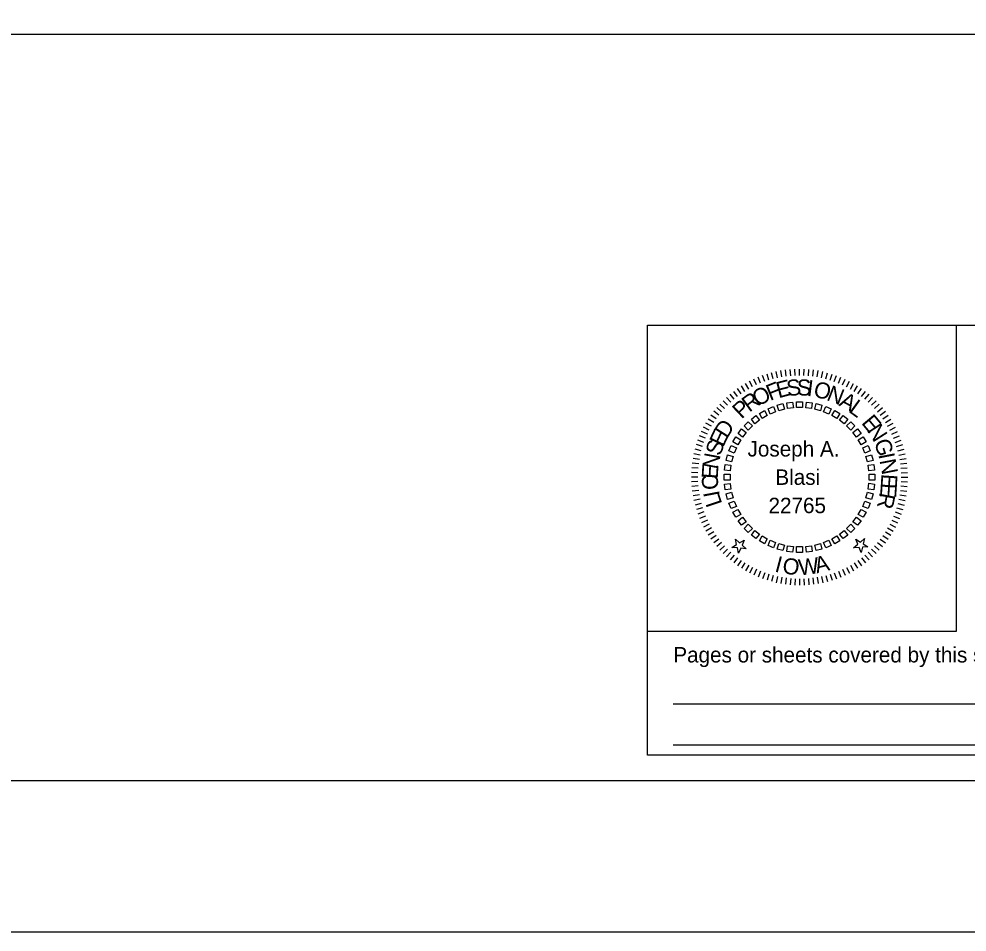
# Model space of a CAD drawing. Extents: x 10040 to 81668, y 7194 to 11018.
# Drawn here: x 11700 to 12436, y 7807 to 8516 of the extents above; entities that cross this region are included whole.
import ezdxf

# ---------------------------------------------------------------- set-up
doc = ezdxf.new("R2010")
doc.units = 0
for name, color, linetype in [('dsnCellElements', 7, 'Continuous'), ('dsnCellsSignature', 7, 'Continuous'), ('dsnTextCpn', 7, 'Continuous'), ('Level 3', 7, 'Continuous'), ('Level 4', 7, 'Continuous')]:
    doc.layers.add(name, color=color, linetype=linetype)

msp = doc.modelspace()

# ---------------------------------------------------------------- linework, layer by layer
at = {"layer": 'dsnCellElements'}
msp.add_lwpolyline([(10039.57, 10000.02), (13360.47, 10000.02), (13360.47, 7806.6), (10039.57, 7806.6)], close=True, dxfattribs=at)
at = {"layer": 'dsnCellsSignature'}
for p, q in [((12428.13, 8040.25), (12428.13, 8278.14)), ((12188.13, 8040.25), (12428.13, 8040.25)), ((12208.2, 7984.02), (12918.13, 7984.02)), ((12208.2, 7952.02), (12918.13, 7952.02))]:
    msp.add_line(p, q, dxfattribs=at)
msp.add_lwpolyline([(12188.13, 8278.14), (12938.13, 8278.14), (12938.13, 7944.02), (12188.13, 7944.02)], close=True, dxfattribs=at)
at = {"layer": 'dsnTextCpn'}
for p, q in [((12282.49, 8235.37), (12280.99, 8240.14)), ((12285.8, 8236.33), (12284.51, 8241.16)), ((12289.15, 8237.15), (12288.07, 8242.03)), ((12292.53, 8237.82), (12291.66, 8242.75)), ((12295.94, 8238.35), (12295.28, 8243.31)), ((12299.37, 8238.72), (12298.93, 8243.71)), ((12302.8, 8238.95), (12302.58, 8243.95)), ((12306.25, 8239.03), (12306.25, 8244.03)), ((12306.25, 8239.03), (12306.25, 8244.03)), ((12309.7, 8238.95), (12309.91, 8243.95)), ((12313.13, 8238.72), (12313.57, 8243.71)), ((12316.56, 8238.35), (12317.21, 8243.31)), ((12319.97, 8237.82), (12320.84, 8242.75)), ((12323.35, 8237.15), (12324.43, 8242.03)), ((12326.7, 8236.33), (12327.99, 8241.16)), ((12330.01, 8235.37), (12331.51, 8240.14)), ((12266.75, 8228.44), (12264.25, 8232.77)), ((12269.77, 8230.1), (12267.46, 8234.53)), ((12272.86, 8231.62), (12270.75, 8236.16)), ((12276.02, 8233.01), (12274.1, 8237.63)), ((12279.23, 8234.26), (12277.52, 8238.96)), ((12333.27, 8234.26), (12334.98, 8238.96)), ((12336.48, 8233.01), (12338.4, 8237.63)), ((12339.64, 8231.62), (12341.75, 8236.15)), ((12342.73, 8230.1), (12345.04, 8234.53)), ((12345.75, 8228.44), (12348.25, 8232.77)), ((12258.15, 8222.7), (12255.11, 8226.67)), ((12260.94, 8224.74), (12258.07, 8228.83)), ((12263.8, 8226.65), (12261.12, 8230.87)), ((12348.7, 8226.65), (12351.38, 8230.87)), ((12351.56, 8224.74), (12354.43, 8228.83)), ((12354.34, 8222.7), (12357.39, 8226.67)), ((12250.39, 8215.89), (12246.85, 8219.42)), ((12252.88, 8218.27), (12249.5, 8221.96)), ((12255.47, 8220.54), (12252.25, 8224.37)), ((12357.03, 8220.54), (12360.25, 8224.37)), ((12359.62, 8218.27), (12363, 8221.95)), ((12362.11, 8215.89), (12365.65, 8219.42)), ((12243.57, 8208.12), (12239.6, 8211.16)), ((12245.73, 8210.8), (12241.9, 8214.02)), ((12248, 8213.4), (12244.32, 8216.77)), ((12364.5, 8213.4), (12368.18, 8216.77)), ((12366.77, 8210.8), (12370.6, 8214.02)), ((12368.93, 8208.12), (12372.89, 8211.16)), ((12239.62, 8202.47), (12235.4, 8205.16)), ((12241.53, 8205.34), (12237.44, 8208.2)), ((12370.97, 8205.34), (12375.06, 8208.2)), ((12372.88, 8202.47), (12377.1, 8205.16)), ((12234.65, 8193.41), (12230.12, 8195.52)), ((12236.17, 8196.5), (12231.74, 8198.81)), ((12237.83, 8199.52), (12233.5, 8202.02)), ((12374.67, 8199.52), (12379, 8202.02)), ((12376.33, 8196.5), (12380.76, 8198.81)), ((12377.85, 8193.41), (12382.38, 8195.52)), ((12232.01, 8187.04), (12227.31, 8188.75)), ((12233.26, 8190.25), (12228.64, 8192.17)), ((12379.24, 8190.25), (12383.86, 8192.17)), ((12380.49, 8187.04), (12385.19, 8188.75)), ((12229.94, 8180.47), (12225.11, 8181.76)), ((12230.9, 8183.78), (12226.13, 8185.28)), ((12381.6, 8183.78), (12386.37, 8185.28)), ((12382.56, 8180.47), (12387.39, 8181.76)), ((12228.45, 8173.74), (12223.52, 8174.61)), ((12229.12, 8177.12), (12224.24, 8178.2)), ((12383.38, 8177.12), (12388.26, 8178.2)), ((12384.05, 8173.74), (12388.98, 8174.61)), ((12227.55, 8166.91), (12222.57, 8167.34)), ((12227.92, 8170.33), (12222.96, 8170.99)), ((12384.58, 8170.33), (12389.53, 8170.99)), ((12384.95, 8166.91), (12389.93, 8167.34)), ((12227.24, 8160.02), (12222.24, 8160.02)), ((12227.32, 8163.47), (12222.33, 8163.69)), ((12385.18, 8163.47), (12390.17, 8163.68)), ((12385.25, 8160.02), (12390.25, 8160.02)), ((12227.32, 8156.58), (12222.33, 8156.36)), ((12227.55, 8153.14), (12222.57, 8152.7)), ((12384.95, 8153.14), (12389.93, 8152.7)), ((12385.18, 8156.57), (12390.17, 8156.36)), ((12227.92, 8149.71), (12222.96, 8149.06)), ((12228.45, 8146.3), (12223.52, 8145.43)), ((12384.05, 8146.3), (12388.98, 8145.43)), ((12384.58, 8149.71), (12389.53, 8149.06)), ((12229.12, 8142.92), (12224.24, 8141.84)), ((12229.94, 8139.57), (12225.11, 8138.28)), ((12230.9, 8136.27), (12226.13, 8134.76)), ((12381.6, 8136.27), (12386.36, 8134.76)), ((12382.56, 8139.57), (12387.39, 8138.28)), ((12383.38, 8142.92), (12388.26, 8141.84)), ((12232.01, 8133), (12227.31, 8131.29)), ((12233.26, 8129.79), (12228.64, 8127.87)), ((12379.24, 8129.79), (12383.86, 8127.87)), ((12380.49, 8133), (12385.19, 8131.29)), ((12234.65, 8126.63), (12230.12, 8124.52)), ((12236.17, 8123.54), (12231.74, 8121.23)), ((12376.33, 8123.54), (12380.76, 8121.23)), ((12377.85, 8126.63), (12382.38, 8124.52)), ((12237.83, 8120.52), (12233.5, 8118.02)), ((12239.62, 8117.57), (12235.4, 8114.89)), ((12241.53, 8114.71), (12237.44, 8111.84)), ((12370.97, 8114.71), (12375.06, 8111.84)), ((12372.88, 8117.57), (12377.1, 8114.89)), ((12374.67, 8120.52), (12379, 8118.02)), ((12243.57, 8111.93), (12239.6, 8108.88)), ((12245.73, 8109.24), (12241.9, 8106.02)), ((12366.77, 8109.24), (12370.6, 8106.02)), ((12368.93, 8111.92), (12372.89, 8108.88)), ((12248, 8106.65), (12244.31, 8103.27)), ((12250.38, 8104.16), (12246.85, 8100.62)), ((12252.87, 8101.77), (12249.5, 8098.09)), ((12255.47, 8099.5), (12252.25, 8095.67)), ((12357.03, 8099.5), (12360.25, 8095.67)), ((12359.62, 8101.77), (12363, 8098.09)), ((12362.11, 8104.16), (12365.65, 8100.62)), ((12364.5, 8106.65), (12368.18, 8103.27)), ((12258.15, 8097.34), (12255.11, 8093.38)), ((12260.93, 8095.3), (12258.07, 8091.21)), ((12263.8, 8093.39), (12261.12, 8089.17)), ((12348.7, 8093.39), (12351.38, 8089.17)), ((12351.56, 8095.3), (12354.43, 8091.21)), ((12354.34, 8097.34), (12357.39, 8093.38)), ((12266.75, 8091.6), (12264.25, 8087.27)), ((12269.77, 8089.94), (12267.46, 8085.51)), ((12272.86, 8088.42), (12270.75, 8083.89)), ((12276.02, 8087.03), (12274.1, 8082.41)), ((12279.23, 8085.78), (12277.52, 8081.08)), ((12333.27, 8085.78), (12334.98, 8081.08)), ((12336.48, 8087.03), (12338.4, 8082.41)), ((12339.64, 8088.42), (12341.75, 8083.89)), ((12342.73, 8089.94), (12345.04, 8085.51)), ((12345.75, 8091.6), (12348.25, 8087.27)), ((12282.49, 8084.67), (12280.99, 8079.91)), ((12285.8, 8083.71), (12284.51, 8078.88)), ((12289.15, 8082.89), (12288.07, 8078.01)), ((12292.53, 8082.22), (12291.66, 8077.29)), ((12295.94, 8081.69), (12295.28, 8076.74)), ((12299.36, 8081.32), (12298.93, 8076.34)), ((12302.8, 8081.09), (12302.58, 8076.1)), ((12306.25, 8081.02), (12306.25, 8076.02)), ((12309.7, 8081.09), (12309.91, 8076.1)), ((12313.13, 8081.32), (12313.57, 8076.34)), ((12316.56, 8081.69), (12317.21, 8076.74)), ((12319.97, 8082.22), (12320.84, 8077.29)), ((12323.35, 8082.89), (12324.43, 8078.01)), ((12326.7, 8083.71), (12327.99, 8078.88)), ((12330.01, 8084.67), (12331.51, 8079.91))]:
    msp.add_line(p, q, dxfattribs=at)
for points in [[(12301.43, 8213.86), (12296.97, 8213.27), (12296.38, 8217.73), (12300.84, 8218.32)], [(12308.5, 8214.02), (12304, 8214.02), (12304, 8218.52), (12308.5, 8218.52)], [(12315.53, 8213.27), (12311.07, 8213.86), (12311.65, 8218.32), (12316.12, 8217.73)], [(12281.2, 8207.92), (12277.3, 8205.66), (12275.05, 8209.56), (12278.95, 8211.81)], [(12287.66, 8210.77), (12283.51, 8209.05), (12281.78, 8213.21), (12285.94, 8214.93)], [(12294.45, 8212.77), (12290.1, 8211.6), (12288.93, 8215.95), (12293.28, 8217.11)], [(12322.4, 8211.6), (12318.05, 8212.77), (12319.22, 8217.11), (12323.57, 8215.95)], [(12328.99, 8209.05), (12324.83, 8210.77), (12326.56, 8214.93), (12330.72, 8213.21)], [(12335.2, 8205.66), (12331.3, 8207.92), (12333.55, 8211.81), (12337.45, 8209.56)], [(12269.65, 8199.8), (12266.47, 8196.62), (12263.29, 8199.8), (12266.47, 8202.98)], [(12275.16, 8204.23), (12271.59, 8201.49), (12268.85, 8205.07), (12272.42, 8207.8)], [(12340.91, 8201.49), (12337.34, 8204.23), (12340.08, 8207.8), (12343.65, 8205.07)], [(12346.03, 8196.62), (12342.84, 8199.8), (12346.03, 8202.98), (12349.21, 8199.8)], [(12264.77, 8194.68), (12262.04, 8191.11), (12258.47, 8193.85), (12261.21, 8197.42)], [(12350.46, 8191.11), (12347.72, 8194.68), (12351.29, 8197.42), (12354.03, 8193.85)], [(12260.6, 8188.97), (12258.36, 8185.07), (12254.46, 8187.32), (12256.71, 8191.22)], [(12354.14, 8185.07), (12351.89, 8188.97), (12355.79, 8191.22), (12358.04, 8187.32)], [(12257.22, 8182.77), (12255.5, 8178.61), (12251.34, 8180.33), (12253.06, 8184.49)], [(12357, 8178.61), (12355.28, 8182.77), (12359.44, 8184.49), (12361.16, 8180.33)], [(12254.67, 8176.17), (12253.5, 8171.82), (12249.16, 8172.99), (12250.32, 8177.34)], [(12359, 8171.83), (12357.83, 8176.17), (12362.18, 8177.34), (12363.34, 8172.99)], [(12253, 8169.3), (12252.42, 8164.84), (12247.95, 8165.43), (12248.54, 8169.89)], [(12360.08, 8164.84), (12359.5, 8169.3), (12363.96, 8169.89), (12364.55, 8165.43)], [(12252.25, 8162.27), (12252.25, 8157.77), (12247.75, 8157.77), (12247.75, 8162.27)], [(12360.25, 8157.77), (12360.25, 8162.27), (12364.75, 8162.27), (12364.75, 8157.77)], [(12252.41, 8155.2), (12253, 8150.74), (12248.54, 8150.15), (12247.95, 8154.62)], [(12359.5, 8150.74), (12360.08, 8155.21), (12364.55, 8154.62), (12363.96, 8150.16)], [(12253.5, 8148.22), (12254.67, 8143.87), (12250.32, 8142.71), (12249.16, 8147.05)], [(12357.83, 8143.87), (12358.99, 8148.22), (12363.34, 8147.05), (12362.18, 8142.71)], [(12255.5, 8141.43), (12257.22, 8137.28), (12253.06, 8135.55), (12251.34, 8139.71)], [(12355.28, 8137.28), (12357, 8141.43), (12361.16, 8139.71), (12359.44, 8135.55)], [(12258.35, 8134.97), (12260.61, 8131.07), (12256.71, 8128.82), (12254.46, 8132.72)], [(12262.04, 8128.93), (12264.78, 8125.36), (12261.21, 8122.62), (12258.47, 8126.19)], [(12347.72, 8125.36), (12350.46, 8128.93), (12354.03, 8126.19), (12351.29, 8122.62)], [(12351.89, 8131.07), (12354.14, 8134.97), (12358.04, 8132.72), (12355.79, 8128.82)], [(12266.47, 8123.43), (12269.65, 8120.24), (12266.47, 8117.06), (12263.29, 8120.24)], [(12342.84, 8120.24), (12346.03, 8123.43), (12349.21, 8120.24), (12346.03, 8117.06)], [(12271.59, 8118.55), (12275.16, 8115.81), (12272.42, 8112.24), (12268.85, 8114.98)], [(12277.3, 8114.38), (12281.2, 8112.13), (12278.95, 8108.23), (12275.05, 8110.48)], [(12331.3, 8112.13), (12335.2, 8114.38), (12337.45, 8110.48), (12333.55, 8108.23)], [(12337.34, 8115.81), (12340.91, 8118.55), (12343.65, 8114.98), (12340.08, 8112.24)], [(12256.53, 8111.75), (12259.68, 8108.9), (12263.37, 8111.03), (12261.64, 8107.14), (12264.8, 8104.29), (12260.57, 8104.74), (12258.84, 8100.85), (12257.96, 8105.02), (12253.73, 8105.46), (12257.41, 8107.58)], [(12283.51, 8110.99), (12287.66, 8109.27), (12285.94, 8105.11), (12281.78, 8106.83)], [(12290.1, 8108.44), (12294.45, 8107.28), (12293.28, 8102.93), (12288.93, 8104.09)], [(12318.05, 8107.27), (12322.4, 8108.44), (12323.57, 8104.09), (12319.22, 8102.93)], [(12324.84, 8109.27), (12328.99, 8110.99), (12330.72, 8106.83), (12326.56, 8105.11)], [(12349.95, 8111.77), (12353.56, 8109.51), (12356.82, 8112.24), (12355.79, 8108.12), (12359.4, 8105.86), (12355.15, 8105.57), (12354.12, 8101.44), (12352.53, 8105.38), (12348.28, 8105.09), (12351.55, 8107.82)], [(12296.97, 8106.77), (12301.43, 8106.19), (12300.84, 8101.72), (12296.38, 8102.31)], [(12304, 8106.02), (12308.5, 8106.02), (12308.5, 8101.52), (12304, 8101.52)], [(12311.07, 8106.19), (12315.53, 8106.77), (12316.12, 8102.31), (12311.65, 8101.73)]]:
    msp.add_lwpolyline(points, close=True, dxfattribs=at)
at = {"layer": 'Level 3'}
msp.add_lwpolyline([(10132.52, 9944.02), (13267.53, 9944.02), (13267.53, 7924.02), (10132.52, 7924.02)], close=True, dxfattribs=at)
msp.add_lwpolyline([(10132.52, 9944.02), (13267.53, 9944.02), (13267.53, 7924.02), (10132.52, 7924.02)], close=True, dxfattribs=at)
at = {"layer": 'Level 4'}
msp.add_lwpolyline([(10868.28, 8853.82), (12518.28, 8853.82), (12518.28, 8503.82), (10868.28, 8503.82)], close=True, dxfattribs=at)

# ---------------------------------------------------------------- texts
at = {"layer": 'dsnCellsSignature'}
msp.add_text('L', height=12.5, rotation=324.24335, dxfattribs=at).set_placement((12343.78, 8211.09))
msp.add_text('Pages or sheets covered by this seal:', height=12, dxfattribs=at).set_placement((12208.2, 8016.02))
at = {"layer": 'dsnTextCpn'}
for s, rotation, p in [('F', 21.77363, (12283.38, 8219.14)), ('E', 14.58234, (12289.94, 8221.27)), ('S', 7.39106, (12296.96, 8222.72)), ('S', 0.19978, (12304.26, 8223.39)), ('I', 353.00849, (12311.59, 8223.22)), ('O', 345.81721, (12316.32, 8222.85)), ('R', 36.1562, (12267.22, 8210)), ('O', 28.96491, (12273.86, 8214.53)), ('N', 338.62592, (12326.56, 8220.13)), ('A', 331.43464, (12336.18, 8215.89)), ('P', 43.34748, (12261.26, 8204.71)), ('D', 57.73005, (12249.9, 8189.5)), ('E', 309.86078, (12353.77, 8202)), ('E', 64.92134, (12246.99, 8182.92)), ('N', 302.6695, (12358.22, 8196.38)), ('S', 72.11262, (12244.78, 8175.91)), ('G', 288.28693, (12363.93, 8187.45)), ('N', 79.30391, (12242.8, 8165.56)), ('I', 281.09564, (12367.39, 8177.6)), ('N', 281.09564, (12368.3, 8172.96)), ('E', 86.49519, (12242.65, 8158.36)), ('C', 93.68648, (12243.35, 8150.47)), ('E', 266.27731, (12369.94, 8162.78)), ('E', 266.27731, (12369.48, 8155.62)), ('I', 100.87776, (12244.43, 8145.85)), ('L', 108.06904, (12246.33, 8139.36)), ('R', 259.08602, (12368.58, 8148.51)), ('I', 345.29061, (12286.37, 8086.79)), ('O', 352.48189, (12292.48, 8085.3)), ('W', 6.86446, (12306.18, 8083.58)), ('A', 14.05574, (12319.59, 8085.14))]:
    msp.add_text(s, height=12.5, rotation=rotation, dxfattribs=at).set_placement(p)
for s, p in [('Joseph A. ', (12265.88, 8176.02)), ('Blasi', (12287.5, 8154.02)), ('22765', (12282.16, 8132.02))]:
    msp.add_text(s, height=12.001, dxfattribs=at).set_placement(p)

doc.saveas('drawing.dxf')
